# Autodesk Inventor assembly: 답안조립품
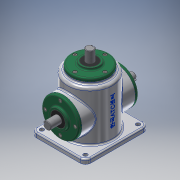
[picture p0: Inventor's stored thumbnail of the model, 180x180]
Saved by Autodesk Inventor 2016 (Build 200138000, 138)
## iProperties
Created: 2021-02
Part Number: 답안조립품
Material: 일반
Document SubType Name: Assembly
Designer: user
Author: user
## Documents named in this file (16)
- C:\Users\user\Desktop\710206V1006\답안조립품.iam
- C:\Users\user\Desktop\710206V1006\본체.ipt
- C:\Users\user\Desktop\710206V1006\메인 베벨기어.ipt
- C:\Users\user\Desktop\710206V1006\메인 축.ipt
- 메인 축.ipt
- C:\Users\user\Desktop\710206V1006\베어링 6203.ipt
- C:\Users\user\Desktop\710206V1006\볼트 M4.ipt
- 볼트 M4.ipt
- C:\Users\user\Desktop\710206V1006\서브 베벨기어.ipt
- C:\Users\user\Desktop\710206V1006\서브 축.ipt
- 서브 축.ipt
- C:\Users\user\Desktop\710206V1006\오일 실.ipt
- 오일 실.ipt
- C:\Users\user\Desktop\710206V1006\커버.ipt
- C:\Users\user\Desktop\710206V1006\키 4x4.ipt
- C:\Users\user\Desktop\710206V1006\키 5x5.ipt
